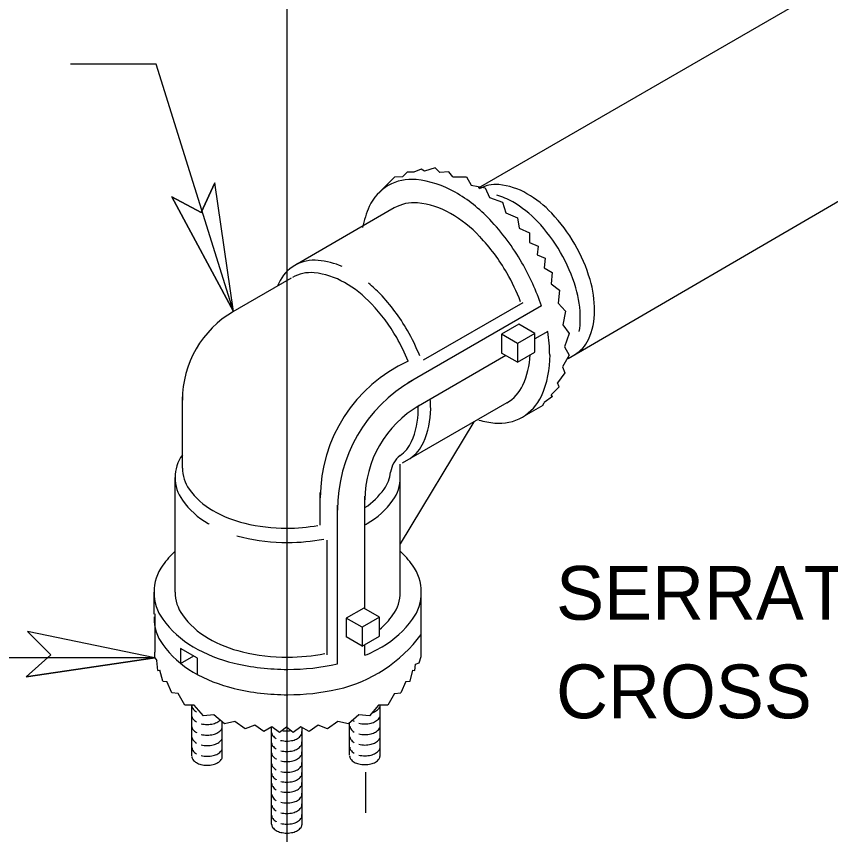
# Model space of a CAD drawing. Extents: x -224.9 to -217.6, y 224 to 234.
# Drawn here: x -220.522 to -219.614, y 230.95 to 231.863 of the extents above; entities that cross this region are included whole.
import ezdxf

# ---------------------------------------------------------------- set-up
doc = ezdxf.new("R2010")
doc.units = 0
for name, color, linetype in [('DETL-DIMS', 7, 'Continuous'), ('DETL-LINE', 7, 'Continuous'), ('DETL-NOTE', 7, 'Continuous')]:
    doc.layers.add(name, color=color, linetype=linetype)

msp = doc.modelspace()

# ---------------------------------------------------------------- linework, layer by layer
at = {"layer": 'DETL-DIMS'}
for p, q in [((-220.22004, 230.82734), (-220.22004, 232.56096)), ((-220.36652, 231.80998), (-220.46194, 231.80998)), ((-220.27993, 231.53398), (-220.36652, 231.80998)), ((-220.31634, 231.6442), (-220.30093, 231.67764)), ((-220.27993, 231.53398), (-220.30093, 231.67764)), ((-220.27993, 231.53398), (-220.34884, 231.66183)), ((-220.34884, 231.66183), (-220.31634, 231.6442)), ((-220.36779, 231.14729), (-220.50999, 231.1766)), ((-220.48382, 231.1507), (-220.50999, 231.1766)), ((-220.36779, 231.14729), (-220.60279, 231.14729)), ((-220.51148, 231.12616), (-220.48382, 231.1507)), ((-220.36779, 231.14729), (-220.51148, 231.12616)), ((-220.13233, 230.9743), (-220.13233, 231.01956))]:
    msp.add_line(p, q, dxfattribs=at)
for points in [[(-220.34884, 231.66183), (-220.27993, 231.53398), (-220.30093, 231.67764), (-220.31634, 231.6442)], [(-220.51148, 231.12616), (-220.36779, 231.14729), (-220.50999, 231.1766), (-220.48382, 231.1507)]]:
    msp.add_lwpolyline(points, close=True, dxfattribs=at)
at = {"layer": 'DETL-LINE'}
for p, q in [((-219.44936, 231.99364), (-220.00723, 231.67156)), ((-219.90663, 231.48157), (-219.33968, 231.81188)), ((-220.05496, 231.69413), (-220.06704, 231.69068)), ((-220.04978, 231.68896), (-220.05496, 231.69413)), ((-220.08646, 231.68939), (-220.09164, 231.68421)), ((-220.0787, 231.68939), (-220.08646, 231.68939)), ((-220.0705, 231.69284), (-220.0787, 231.68939)), ((-220.06704, 231.69068), (-220.0705, 231.69284)), ((-220.03966, 231.68973), (-220.04978, 231.68896)), ((-220.03542, 231.6841), (-220.03966, 231.68973)), ((-220.10027, 231.68378), (-220.11782, 231.66641)), ((-220.09164, 231.68421), (-220.10027, 231.68378)), ((-220.03542, 231.6841), (-220.02023, 231.68403)), ((-220.02023, 231.68403), (-220.01501, 231.675)), ((-220.01501, 231.675), (-219.99936, 231.67198)), ((-219.99936, 231.67198), (-219.99451, 231.66105)), ((-219.99451, 231.66105), (-219.97974, 231.65588)), ((-220.10062, 231.64942), (-220.21166, 231.58531)), ((-219.97974, 231.65588), (-219.9762, 231.64417)), ((-219.9762, 231.64417), (-219.96311, 231.63841)), ((-219.96311, 231.63841), (-219.96133, 231.62685)), ((-219.96133, 231.62685), (-219.94997, 231.62169)), ((-219.94997, 231.62169), (-219.94984, 231.61097)), ((-219.94984, 231.61097), (-219.94001, 231.60679)), ((-219.94001, 231.60679), (-219.94124, 231.59712)), ((-219.94124, 231.59712), (-219.93225, 231.59336)), ((-219.93225, 231.59336), (-219.93355, 231.58275)), ((-219.93355, 231.58275), (-219.92433, 231.57728)), ((-219.92433, 231.57728), (-219.92553, 231.56486)), ((-220.21565, 231.57109), (-220.2833, 231.53203)), ((-219.92553, 231.56486), (-219.91642, 231.55754)), ((-219.91642, 231.55754), (-219.91797, 231.54332)), ((-219.93656, 231.54001), (-220.08536, 231.4541)), ((-219.95731, 231.54354), (-220.06835, 231.47944)), ((-219.91797, 231.54332), (-219.9096, 231.5344)), ((-219.9096, 231.5344), (-219.91251, 231.51902)), ((-219.96168, 231.51961), (-219.98106, 231.50843)), ((-219.94392, 231.50936), (-219.96168, 231.51961)), ((-219.92946, 231.51155), (-219.94392, 231.50321)), ((-219.91251, 231.51902), (-219.90547, 231.50935)), ((-219.98106, 231.50843), (-219.98106, 231.48738)), ((-219.9633, 231.49817), (-219.98106, 231.50843)), ((-219.94392, 231.50936), (-219.9633, 231.49817)), ((-219.94392, 231.48831), (-219.94392, 231.50936)), ((-219.90547, 231.50935), (-219.91068, 231.49429)), ((-219.9633, 231.49817), (-219.9633, 231.47712)), ((-219.91068, 231.49429), (-219.90547, 231.48526)), ((-219.97619, 231.48457), (-220.0763, 231.42677)), ((-219.9633, 231.47712), (-219.98106, 231.48738)), ((-219.9633, 231.47712), (-219.94392, 231.48831)), ((-219.90547, 231.48526), (-219.913, 231.47207)), ((-219.91025, 231.46558), (-219.91844, 231.45417)), ((-219.913, 231.47207), (-219.91025, 231.46558)), ((-219.91655, 231.44987), (-219.92553, 231.44087)), ((-219.91655, 231.44987), (-219.91844, 231.45417)), ((-220.33713, 231.35913), (-220.33713, 231.43879)), ((-219.9243, 231.43907), (-219.93353, 231.43221)), ((-219.9243, 231.43907), (-219.92553, 231.44087)), ((-219.97503, 231.43188), (-220.09193, 231.36439)), ((-219.93497, 231.429), (-219.95584, 231.41695)), ((-219.93497, 231.429), (-219.95584, 231.41695)), ((-219.93497, 231.429), (-219.93353, 231.43221)), ((-220.01202, 231.41052), (-220.09403, 231.27465)), ((-220.09403, 231.35554), (-220.09407, 231.36333)), ((-220.34522, 231.22056), (-220.34522, 231.34852)), ((-220.09403, 231.22056), (-220.09403, 231.35554)), ((-220.18321, 231.29553), (-220.18321, 231.33168)), ((-220.13338, 231.20207), (-220.13338, 231.32791)), ((-220.16412, 231.14045), (-220.16412, 231.31768)), ((-220.17557, 231.15078), (-220.17557, 231.27874)), ((-220.36877, 231.19614), (-220.36877, 231.2205)), ((-220.07068, 231.18883), (-220.07068, 231.21894)), ((-220.13481, 231.20289), (-220.15419, 231.19171)), ((-220.11704, 231.19264), (-220.13481, 231.20289)), ((-220.36779, 231.19624), (-220.36779, 231.15354)), ((-220.13642, 231.18145), (-220.15419, 231.19171)), ((-220.15419, 231.19171), (-220.15419, 231.17066)), ((-220.11704, 231.19264), (-220.13642, 231.18145)), ((-220.11704, 231.17159), (-220.11704, 231.19264)), ((-220.07068, 231.1489), (-220.07068, 231.18883)), ((-220.13642, 231.18145), (-220.13642, 231.1604)), ((-220.13642, 231.1604), (-220.15419, 231.17066)), ((-220.13642, 231.1604), (-220.11704, 231.17159)), ((-220.32025, 231.14697), (-220.33911, 231.15786)), ((-220.33911, 231.15786), (-220.33911, 231.1409)), ((-220.13338, 231.15008), (-220.13338, 231.16216)), ((-220.36779, 231.14729), (-220.36779, 231.15354)), ((-220.36779, 231.14729), (-220.36576, 231.14448)), ((-220.33911, 231.1409), (-220.32442, 231.14938)), ((-220.32025, 231.12853), (-220.32025, 231.14697)), ((-220.07294, 231.14163), (-220.07068, 231.1489)), ((-220.36445, 231.13321), (-220.36576, 231.14448)), ((-220.07772, 231.13321), (-220.07691, 231.14016)), ((-220.07691, 231.14016), (-220.07294, 231.14163)), ((-220.36445, 231.13321), (-220.36231, 231.13337)), ((-220.35905, 231.12127), (-220.36231, 231.13337)), ((-220.08312, 231.12127), (-220.07986, 231.13337)), ((-220.07986, 231.13337), (-220.07772, 231.13321)), ((-220.35905, 231.12127), (-220.35444, 231.12076)), ((-220.34873, 231.10813), (-220.35444, 231.12076)), ((-220.08773, 231.12076), (-220.09344, 231.10813)), ((-220.08773, 231.12076), (-220.08312, 231.12127)), ((-220.34183, 231.10728), (-220.34873, 231.10813)), ((-220.33428, 231.09435), (-220.34183, 231.10728)), ((-220.10034, 231.10728), (-220.10789, 231.09435)), ((-220.10034, 231.10728), (-220.09344, 231.10813)), ((-220.32399, 231.09435), (-220.33428, 231.09435)), ((-220.32653, 231.0379), (-220.32653, 231.09435)), ((-220.3137, 231.08246), (-220.32399, 231.09435)), ((-220.11818, 231.09435), (-220.12847, 231.08246)), ((-220.10789, 231.09435), (-220.11818, 231.09435)), ((-220.1166, 231.03845), (-220.1166, 231.09435)), ((-220.30197, 231.08371), (-220.3137, 231.08246)), ((-220.29027, 231.07364), (-220.30197, 231.08371)), ((-220.1402, 231.08371), (-220.1519, 231.07364)), ((-220.12847, 231.08246), (-220.1402, 231.08371)), ((-220.29264, 231.03783), (-220.29264, 231.07568)), ((-220.27852, 231.07639), (-220.29027, 231.07364)), ((-220.26714, 231.06805), (-220.27852, 231.07639)), ((-220.16365, 231.07639), (-220.17503, 231.06805)), ((-220.1519, 231.07364), (-220.16365, 231.07639)), ((-220.15049, 231.03852), (-220.15049, 231.07485)), ((-220.25639, 231.07223), (-220.26714, 231.06805)), ((-220.24638, 231.06507), (-220.25639, 231.07223)), ((-220.23716, 231.07025), (-220.24638, 231.06507)), ((-220.23752, 230.96154), (-220.23752, 231.06941)), ((-220.22873, 231.06391), (-220.23716, 231.07025)), ((-220.22109, 231.06974), (-220.22873, 231.06391)), ((-220.21344, 231.06391), (-220.22109, 231.06974)), ((-220.20501, 231.07025), (-220.21344, 231.06391)), ((-220.19579, 231.06507), (-220.20501, 231.07025)), ((-220.20363, 230.96178), (-220.20363, 231.06948)), ((-220.18578, 231.07223), (-220.19579, 231.06507)), ((-220.17503, 231.06805), (-220.18578, 231.07223))]:
    msp.add_line(p, q, dxfattribs=at)
for centre, radius, start, end in [((-220.08151, 231.62974), 0.0516, 84.34287, 120), ((-220.08715, 231.5728), 0.10882, 60, 84.34287), ((-219.98752, 231.63869), 0.03693, 84.34287, 120), ((-219.99156, 231.59794), 0.07788, 60, 84.34287), ((-220.08151, 231.62974), 0.0516, 120, 155.65713), ((-220.11796, 231.51945), 0.17043, 43.44948, 60), ((-220.0075, 231.58873), 0.07788, 60, 74.12922), ((-220.0136, 231.55975), 0.12198, 43.44948, 60), ((-220.02938, 231.60616), 0.10882, 155.65713, 168.58916), ((-220.0789, 231.61178), 0.04346, 84.34287, 120), ((-220.08364, 231.56383), 0.09164, 60, 84.34287), ((-220.02955, 231.55054), 0.12198, 43.44948, 60), ((-220.10959, 231.5189), 0.14352, 43.44948, 60), ((-220.05883, 231.5169), 0.18428, 30, 43.44948), ((-220.18115, 231.45958), 0.25747, 30, 43.44948), ((-220.07477, 231.5077), 0.18428, 30, 43.44948), ((-220.1628, 231.46849), 0.21682, 30, 43.44948), ((-220.05883, 231.5169), 0.18428, 16.55052, 30), ((-220.07477, 231.5077), 0.18428, 16.55052, 30), ((-220.18993, 231.54768), 0.04346, 120, 155.65713), ((-220.18993, 231.54768), 0.04346, 84.34287, 120), ((-220.19468, 231.49973), 0.09164, 66.90378, 84.34287), ((-220.18115, 231.45958), 0.25747, 18.20151, 30), ((-220.19419, 231.53701), 0.04025, 84.34287, 120), ((-220.19859, 231.4926), 0.08487, 60, 84.34287), ((-220.1628, 231.46849), 0.21682, 20.61025, 30), ((-220.22262, 231.45099), 0.13292, 43.44948, 60), ((-219.99911, 231.53465), 0.12198, 0, 16.55052), ((-220.14603, 231.52782), 0.09164, 155.65713, 157.92516), ((-220.22062, 231.4548), 0.14352, 43.44948, 50.47493), ((-220.01506, 231.52545), 0.12198, 360, 16.55052), ((-220.27383, 231.40439), 0.21682, 30, 43.44948), ((-220.2719, 231.40431), 0.2008, 30, 43.44948), ((-220.22273, 231.4349), 0.1144, 120, 180), ((-220.09254, 231.48937), 0.14352, 16.23905, 16.55052), ((-219.95502, 231.53465), 0.07788, 335.65713, 360), ((-219.97096, 231.52545), 0.07788, 349.68364, 0), ((-220.27383, 231.40439), 0.21682, 21.62725, 30), ((-220.09771, 231.48438), 0.17043, 0.2972, 9.174), ((-220.2719, 231.40431), 0.2008, 21.70306, 30), ((-219.91771, 231.51777), 0.03693, 300, 335.65713), ((-220.04065, 231.48937), 0.09164, 335.65713, 357.46064), ((-220.03569, 231.48429), 0.10882, 335.65713, 0.6188), ((-220.01585, 231.32599), 0.16736, 114.49043, 180), ((-219.99675, 231.312), 0.16736, 120, 180), ((-219.99676, 231.46951), 0.04346, 299.99999, 335.65713), ((-219.98356, 231.4607), 0.0516, 300, 335.65713), ((-220.01209, 231.3238), 0.12129, 120, 180), ((-220.20357, 231.42527), 0.14352, 360, 4.25866), ((-220.15878, 231.42364), 0.08487, 335.65713, 0), ((-220.20683, 231.42364), 0.13292, 0, 1.9263), ((-220.15169, 231.42527), 0.09164, 335.65713, 0), ((-219.97792, 231.51764), 0.10882, 254.90696, 264.34287), ((-219.98356, 231.4607), 0.0516, 264.34287, 300), ((-220.11812, 231.40525), 0.04025, 306.64536, 335.65713), ((-220.10779, 231.40541), 0.04346, 304.80323, 335.65713), ((-220.30176, 231.34852), 0.04346, 144.48177, 215.65713), ((-220.07803, 231.35136), 0.02692, 126.64535, 173.35464), ((-220.29689, 231.35913), 0.04025, 180, 215.65713), ((-220.14475, 231.35913), 0.04025, 324.34287, 353.35464), ((-220.13748, 231.34852), 0.04346, 324.34287, 0), ((-220.26063, 231.38515), 0.08487, 215.65713, 240), ((-220.181, 231.38515), 0.08487, 304.13929, 324.34287), ((-220.26261, 231.3766), 0.09164, 215.65713, 240), ((-220.17663, 231.3766), 0.09164, 300, 324.34287), ((-220.23661, 231.42676), 0.13292, 240, 256.55052), ((-220.23667, 231.42154), 0.14352, 240, 240.60368), ((-220.22082, 231.49278), 0.2008, 256.55052, 270), ((-220.22082, 231.49278), 0.2008, 270, 280.03284), ((-220.20258, 231.42154), 0.14352, 298.82661, 300), ((-220.23667, 231.42154), 0.14352, 253.94899, 256.55052), ((-220.21962, 231.49283), 0.21682, 256.55052, 270), ((-220.21962, 231.49283), 0.21682, 270, 280.68215), ((-220.27068, 231.18714), 0.10882, 133.23475, 144.34287), ((-220.16858, 231.18714), 0.10882, 35.65713, 46.76004), ((-220.31717, 231.2205), 0.0516, 144.34287, 180), ((-220.12209, 231.2205), 0.0516, 360, 35.65713), ((-220.31717, 231.2205), 0.0516, 180, 215.65713), ((-220.30176, 231.22056), 0.04346, 179.99999, 215.65713), ((-220.13748, 231.22056), 0.04346, 324.34287, 0), ((-220.12209, 231.2205), 0.0516, 324.34287, 0), ((-220.31717, 231.19223), 0.0516, 179.13426, 180), ((-220.31717, 231.19223), 0.0516, 180, 215.65713), ((-220.26261, 231.24864), 0.09164, 215.65713, 240), ((-220.17663, 231.24864), 0.09164, 310.56221, 324.34287), ((-220.27068, 231.25385), 0.10882, 215.65713, 240), ((-220.16858, 231.25385), 0.10882, 300, 324.34287), ((-220.19939, 231.26777), 0.15954, 282.77128, 323.74609), ((-220.23667, 231.29357), 0.14352, 240, 256.55052), ((-220.27068, 231.22558), 0.10882, 215.65713, 240), ((-220.23987, 231.30721), 0.17043, 240, 256.55052), ((-220.19938, 231.30721), 0.17043, 292.78629, 300), ((-220.21962, 231.36486), 0.21682, 256.55052, 270), ((-220.21962, 231.36486), 0.21682, 270, 281.03585), ((-220.21963, 231.39186), 0.25747, 256.55052, 270), ((-220.21963, 231.39186), 0.25747, 270, 282.45065), ((-220.23987, 231.27894), 0.17043, 240, 256.55052), ((-220.21963, 231.36359), 0.25747, 256.55052, 270), ((-220.21963, 231.36359), 0.25747, 270, 282.45065), ((-220.32063, 231.09398), 0.00586, 180.41839, 215.65713), ((-220.12765, 231.09843), 0.01236, 300, 324.34287), ((-220.12236, 231.09464), 0.00586, 324.34287, 349.29111), ((-220.32063, 231.0827), 0.00586, 187.40554, 215.65713), ((-220.31535, 231.09777), 0.01236, 215.65713, 240), ((-220.31185, 231.10383), 0.01937, 240, 240.59898), ((-220.13115, 231.10449), 0.01937, 287.2256, 300), ((-220.12236, 231.08336), 0.00586, 324.34287, 349.29111), ((-220.31535, 231.08649), 0.01236, 215.65713, 240), ((-220.31185, 231.09255), 0.01937, 240, 240.59898), ((-220.31178, 231.09259), 0.01937, 256.50739, 256.55052), ((-220.30948, 231.10221), 0.02926, 256.55052, 270), ((-220.30948, 231.10221), 0.02926, 270, 283.44948), ((-220.30718, 231.09259), 0.01937, 283.44948, 300), ((-220.30368, 231.08652), 0.01236, 300, 314.55854), ((-220.13931, 231.08711), 0.01236, 230.00977, 240), ((-220.13581, 231.09317), 0.01937, 240, 240.59898), ((-220.13575, 231.09321), 0.01937, 256.50739, 256.55052), ((-220.13345, 231.10283), 0.02926, 256.55052, 270), ((-220.13345, 231.10283), 0.02926, 270, 283.44948), ((-220.13115, 231.09321), 0.01937, 283.44948, 300), ((-220.12765, 231.08715), 0.01236, 300, 324.34287), ((-220.32056, 231.07077), 0.00586, 184.61345, 215.65713), ((-220.31528, 231.07456), 0.01236, 215.65713, 240), ((-220.31178, 231.08062), 0.01937, 240, 240.59898), ((-220.30718, 231.08062), 0.01937, 283.44948, 300), ((-220.30368, 231.07456), 0.01236, 300, 324.34287), ((-220.2984, 231.07077), 0.00586, 324.34287, 360), ((-220.2984, 231.07077), 0.00586, 0, 10.26118), ((-220.23167, 231.06412), 0.00586, 181.08351, 215.65713), ((-220.22101, 231.09491), 0.02926, 260.36713, 270), ((-220.22101, 231.09491), 0.02926, 270, 279.38305), ((-220.20957, 231.06415), 0.00586, 324.34287, 0), ((-220.20957, 231.06415), 0.00586, 360, 10.26118), ((-220.14453, 231.07139), 0.00586, 184.61345, 215.65713), ((-220.13925, 231.07518), 0.01236, 215.65713, 240), ((-220.13575, 231.08124), 0.01937, 240, 240.59898), ((-220.13115, 231.08124), 0.01937, 283.44948, 300), ((-220.12765, 231.07518), 0.01236, 300, 324.34287), ((-220.12236, 231.07139), 0.00586, 324.34287, 349.29111), ((-220.32056, 231.05909), 0.00586, 185.23545, 215.65713), ((-220.31528, 231.06288), 0.01236, 215.65713, 240), ((-220.31178, 231.08062), 0.01937, 256.50739, 256.55052), ((-220.30948, 231.09024), 0.02926, 256.55052, 270), ((-220.30948, 231.09024), 0.02926, 270, 283.44948), ((-220.30368, 231.06288), 0.01236, 300, 324.34287), ((-220.2984, 231.05909), 0.00586, 324.34287, 0), ((-220.2984, 231.05909), 0.00586, 360, 10.26118), ((-220.22639, 231.06791), 0.01236, 215.65713, 240), ((-220.22289, 231.07397), 0.01937, 240, 240.59898), ((-220.22295, 231.07401), 0.01937, 256.50739, 256.55052), ((-220.22065, 231.08363), 0.02926, 256.55052, 270), ((-220.22065, 231.08363), 0.02926, 270, 283.44948), ((-220.21835, 231.07401), 0.01937, 283.44948, 300), ((-220.21485, 231.06794), 0.01236, 300, 324.34287), ((-220.14453, 231.05971), 0.00586, 185.23545, 215.65713), ((-220.13925, 231.0635), 0.01236, 215.65713, 240), ((-220.13575, 231.08124), 0.01937, 256.50739, 256.55052), ((-220.13345, 231.09086), 0.02926, 256.55052, 270), ((-220.13345, 231.09086), 0.02926, 270, 283.44948), ((-220.12765, 231.0635), 0.01236, 300, 324.34287), ((-220.12236, 231.05971), 0.00586, 324.34287, 349.29111), ((-220.3206, 231.04711), 0.00586, 180.80273, 215.65713), ((-220.31178, 231.06895), 0.01937, 240, 240.59898), ((-220.31178, 231.06895), 0.01937, 256.50739, 256.55052), ((-220.30948, 231.07857), 0.02926, 256.55052, 270), ((-220.30948, 231.07857), 0.02926, 270, 283.44948), ((-220.30718, 231.06895), 0.01937, 283.44948, 300), ((-220.2984, 231.04713), 0.00586, 324.34287, 360), ((-220.2984, 231.04713), 0.00586, 360, 10.26118), ((-220.23164, 231.05258), 0.00586, 181.29595, 215.65713), ((-220.22636, 231.05637), 0.01236, 215.65713, 240), ((-220.22286, 231.06243), 0.01937, 240, 240.59898), ((-220.21832, 231.06246), 0.01937, 283.44948, 300), ((-220.21482, 231.0564), 0.01236, 300, 324.34287), ((-220.20954, 231.05261), 0.00586, 324.34287, 360), ((-220.20954, 231.05261), 0.00586, 0, 10.26118), ((-220.14457, 231.04773), 0.00586, 180.80273, 215.65713), ((-220.13575, 231.06957), 0.01937, 240, 240.59898), ((-220.13575, 231.06957), 0.01937, 256.50739, 256.55052), ((-220.13345, 231.07919), 0.02926, 256.55052, 270), ((-220.13345, 231.07919), 0.02926, 270, 283.44948), ((-220.13115, 231.06957), 0.01937, 283.44948, 300), ((-220.12236, 231.04775), 0.00586, 324.34287, 355.60326), ((-220.32065, 231.0372), 0.00586, 179.30338, 180), ((-220.32065, 231.0372), 0.00586, 180, 215.65713), ((-220.31532, 231.0509), 0.01236, 215.65713, 240), ((-220.31182, 231.05696), 0.01937, 240, 240.59898), ((-220.31178, 231.05698), 0.01937, 256.50739, 256.55052), ((-220.30948, 231.0666), 0.02926, 256.55052, 270), ((-220.30948, 231.0666), 0.02926, 270, 283.44948), ((-220.30718, 231.05698), 0.01937, 283.44948, 300), ((-220.30368, 231.05092), 0.01236, 300, 324.34287), ((-220.29848, 231.0372), 0.00586, 324.34287, 360), ((-220.29848, 231.0372), 0.00586, 360, 3.0559), ((-220.23164, 231.04129), 0.00586, 181.08351, 215.65713), ((-220.22636, 231.04508), 0.01236, 215.65713, 240), ((-220.22292, 231.06246), 0.01937, 256.50739, 256.55052), ((-220.22062, 231.07208), 0.02926, 256.55052, 270), ((-220.22062, 231.07208), 0.02926, 270, 283.44948), ((-220.21482, 231.04512), 0.01236, 300, 324.34287), ((-220.20954, 231.04133), 0.00586, 324.34287, 360), ((-220.20954, 231.04133), 0.00586, 360, 10.26118), ((-220.14461, 231.03783), 0.00586, 179.30338, 180), ((-220.14461, 231.03783), 0.00586, 180, 215.65713), ((-220.13928, 231.05152), 0.01236, 215.65713, 240), ((-220.13578, 231.05758), 0.01937, 240, 240.59898), ((-220.13575, 231.0576), 0.01937, 256.50739, 256.55052), ((-220.13345, 231.06722), 0.02926, 256.55052, 270), ((-220.13345, 231.06722), 0.02926, 270, 283.44948), ((-220.13115, 231.0576), 0.01937, 283.44948, 300), ((-220.12765, 231.05154), 0.01236, 300, 324.34287), ((-220.12245, 231.03783), 0.00586, 324.34287, 0), ((-220.12245, 231.03783), 0.00586, 360, 3.0559), ((-220.31537, 231.04099), 0.01236, 215.65713, 240), ((-220.31187, 231.04706), 0.01937, 240, 256.55052), ((-220.30957, 231.05668), 0.02926, 256.55052, 270), ((-220.30957, 231.05668), 0.02926, 270, 283.44948), ((-220.30727, 231.04706), 0.01937, 283.44948, 300), ((-220.30377, 231.04099), 0.01236, 300, 324.34287), ((-220.23165, 231.02932), 0.00586, 179.9472, 180), ((-220.23165, 231.02932), 0.00586, 180, 215.65713), ((-220.22286, 231.05115), 0.01937, 240, 240.59898), ((-220.22292, 231.05118), 0.01937, 256.50739, 256.55052), ((-220.22062, 231.0608), 0.02926, 256.55052, 270), ((-220.22062, 231.0608), 0.02926, 270, 283.44948), ((-220.21832, 231.05118), 0.01937, 283.44948, 300), ((-220.20954, 231.02936), 0.00586, 324.34287, 360), ((-220.20954, 231.02936), 0.00586, 0, 10.26118), ((-220.13933, 231.04162), 0.01236, 215.65713, 240), ((-220.13583, 231.04768), 0.01937, 240, 256.55052), ((-220.13353, 231.0573), 0.02926, 256.55052, 270), ((-220.13353, 231.0573), 0.02926, 270, 283.44948), ((-220.13123, 231.04768), 0.01937, 283.44948, 300), ((-220.12773, 231.04162), 0.01236, 300, 324.34287), ((-220.23161, 231.01824), 0.00586, 181.29595, 215.65713), ((-220.22637, 231.03311), 0.01236, 215.65713, 240), ((-220.22287, 231.03918), 0.01937, 240, 240.59898), ((-220.22292, 231.03921), 0.01937, 256.50739, 256.55052), ((-220.22062, 231.04883), 0.02926, 256.55052, 270), ((-220.22062, 231.04883), 0.02926, 270, 283.44948), ((-220.21832, 231.03921), 0.01937, 283.44948, 300), ((-220.21482, 231.03315), 0.01236, 300, 324.34287), ((-220.20952, 231.01828), 0.00586, 324.34287, 360), ((-220.20952, 231.01828), 0.00586, 0, 10.26118), ((-220.22633, 231.02203), 0.01236, 215.65713, 240), ((-220.22283, 231.0281), 0.01937, 240, 240.59898), ((-220.22291, 231.02813), 0.01937, 256.50739, 256.55052), ((-220.22061, 231.03775), 0.02926, 256.55052, 270), ((-220.22061, 231.03775), 0.02926, 270, 283.44948), ((-220.21831, 231.02813), 0.01937, 283.44948, 300), ((-220.21481, 231.02207), 0.01236, 300, 324.34287), ((-220.23161, 231.00696), 0.00586, 181.08351, 215.65713), ((-220.22633, 231.01075), 0.01236, 215.65713, 240), ((-220.22283, 231.01681), 0.01937, 240, 240.59898), ((-220.21831, 231.01685), 0.01937, 283.44948, 300), ((-220.21481, 231.01079), 0.01236, 300, 324.34287), ((-220.20952, 231.007), 0.00586, 324.34287, 360), ((-220.20952, 231.007), 0.00586, 360, 10.26118), ((-220.23157, 230.99503), 0.00586, 184.61345, 215.65713), ((-220.22629, 230.99882), 0.01236, 215.65713, 240), ((-220.22291, 231.01685), 0.01937, 256.50739, 256.55052), ((-220.22061, 231.02647), 0.02926, 256.55052, 270), ((-220.22061, 231.02647), 0.02926, 270, 283.44948), ((-220.21481, 230.99882), 0.01236, 300, 324.34287), ((-220.20952, 230.99503), 0.00586, 324.34287, 360), ((-220.20952, 230.99503), 0.00586, 0, 10.26118), ((-220.23157, 230.98336), 0.00586, 185.23545, 215.65713), ((-220.22279, 231.00488), 0.01937, 240, 240.59898), ((-220.22291, 231.00488), 0.01937, 256.50739, 256.55052), ((-220.22061, 231.0145), 0.02926, 256.55052, 270), ((-220.22061, 231.0145), 0.02926, 270, 283.44948), ((-220.21831, 231.00488), 0.01937, 283.44948, 300), ((-220.20952, 230.98336), 0.00586, 324.34287, 360), ((-220.20952, 230.98336), 0.00586, 360, 10.26118), ((-220.22629, 230.98715), 0.01236, 215.65713, 240), ((-220.22279, 230.99321), 0.01937, 240, 240.59898), ((-220.22291, 230.99321), 0.01937, 256.50739, 256.55052), ((-220.22061, 231.00283), 0.02926, 256.55052, 270), ((-220.22061, 231.00283), 0.02926, 270, 283.44948), ((-220.21831, 230.99321), 0.01937, 283.44948, 300), ((-220.21481, 230.98715), 0.01236, 300, 324.34287), ((-220.20952, 230.97139), 0.00586, 360, 10.26118), ((-220.23161, 230.97137), 0.00586, 180.80273, 215.65713), ((-220.22633, 230.97516), 0.01236, 215.65713, 240), ((-220.22282, 230.98122), 0.01937, 240, 240.59898), ((-220.21831, 230.98124), 0.01937, 283.44948, 300), ((-220.21481, 230.97518), 0.01236, 300, 324.34287), ((-220.20952, 230.97139), 0.00586, 324.34287, 360), ((-220.23166, 230.96147), 0.00586, 179.30338, 180), ((-220.23166, 230.96147), 0.00586, 180, 215.65713), ((-220.22637, 230.96526), 0.01236, 215.65713, 240), ((-220.22287, 230.97132), 0.01937, 240, 256.55052), ((-220.22291, 230.98124), 0.01937, 256.50739, 256.55052), ((-220.22061, 230.99086), 0.02926, 256.55052, 270), ((-220.22061, 230.99086), 0.02926, 270, 283.44948), ((-220.21827, 230.97132), 0.01937, 283.44948, 300), ((-220.21477, 230.96526), 0.01236, 300, 324.34287), ((-220.20949, 230.96147), 0.00586, 324.34287, 0), ((-220.20949, 230.96147), 0.00586, 360, 3.0559), ((-220.22057, 230.98094), 0.02926, 256.55052, 270), ((-220.22057, 230.98094), 0.02926, 270, 283.44948)]:
    msp.add_arc(centre, radius, start, end, dxfattribs=at)

# ---------------------------------------------------------------- texts
at = {"layer": 'DETL-NOTE'}
for s, p in [('SERRATED', (-219.92011, 231.18981)), ('CROSS', (-219.92011, 231.07981))]:
    msp.add_text(s, height=0.06, dxfattribs=at).set_placement(p)

doc.saveas('drawing.dxf')
